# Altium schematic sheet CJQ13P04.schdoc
size 127 x 101 mm
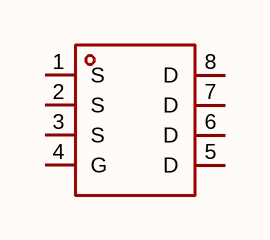
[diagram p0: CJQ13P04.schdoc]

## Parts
Q?  cjq13p04  [SOP-8_L4.9-W3.9-P1.27-LS6.0-BL-1]  (value not drawn)

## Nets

Not connected (* = marked no-connect by the designer): Q? 1(S) 2(S) 3(S) 4(G) 5(D) 6(D) 7(D) 8(D)

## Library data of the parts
Q? = cjq13p04: 数量:1个P沟道;漏源电压(Vdss):40V;连续漏极电流(Id):13A;导通电阻(RDS(on)):11mΩ@10V;耗散功率(Pd):4W;阈值电压(Vgs(th)):1.5V;; Manufacturer: CJ(江苏长电/长晶); AddInBom: yes; ModelId: 75c24a7891ee4dd6bdac16a7163ff87e; ModelTransform: 192.913,236.22,0,0,0,0,0,0,0; Number: 1个P沟道; Drain to Source Voltage: 40V; Current - Continuous Drain(Id): 13A; Pd - Power Dissipation: 4W; Gate Threshold Voltage (Vgs(th)): 1.5V; Gate Charge(Qg): 22.2nC@4.5V; Input Capacitance(Ciss): 2.626nF; Reverse Transfer Capacitance (Crss@Vds): 176pF; Type: P沟道; Output Capacitance(Coss): 262pF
